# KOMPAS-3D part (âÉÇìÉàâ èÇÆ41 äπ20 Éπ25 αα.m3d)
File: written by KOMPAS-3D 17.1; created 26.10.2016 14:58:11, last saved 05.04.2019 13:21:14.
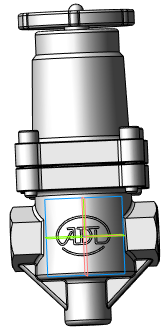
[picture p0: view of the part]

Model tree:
1. Операция без истории:2  (labels: Сталь 20  ГОСТ 1050-88)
